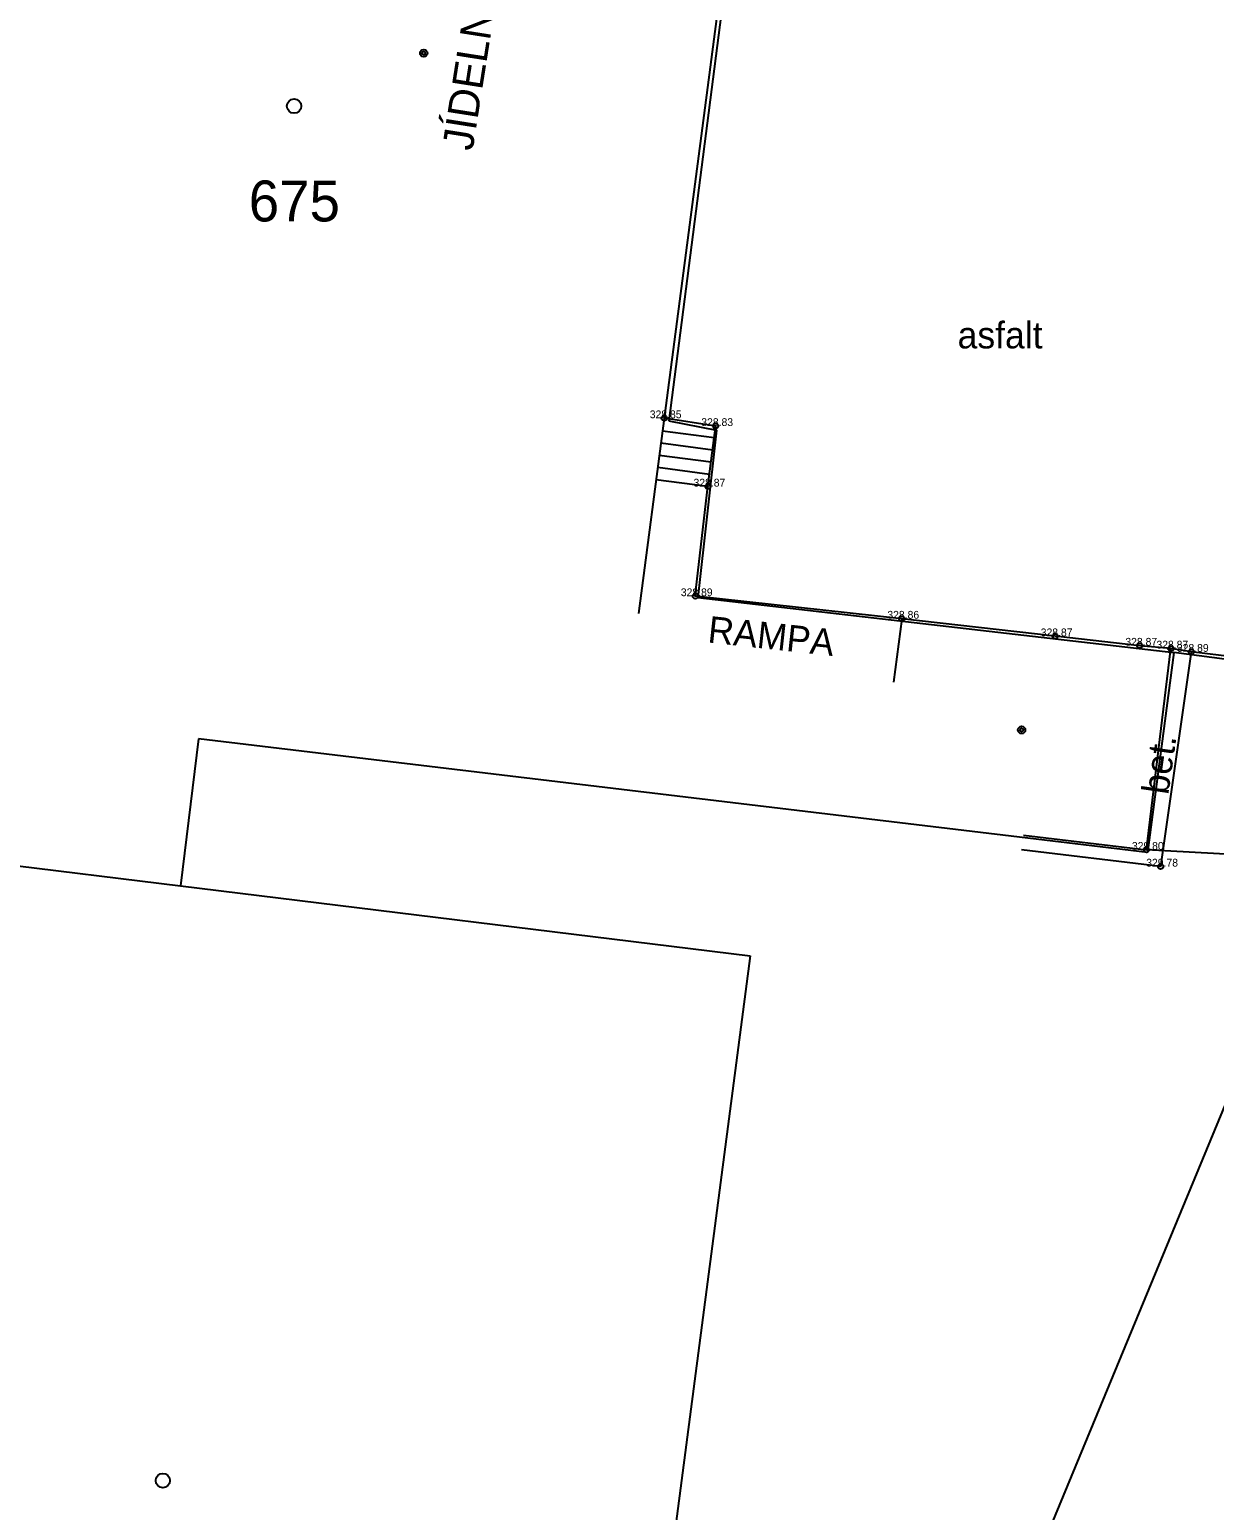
# Model space of a CAD drawing. Extents: x -643859 to -643594, y -1190913 to -1190609.
# Drawn here: x -643791.29 to -643762.32, y -1190846.99 to -1190810.79 of the extents above; entities that cross this region are included whole.
import ezdxf

# ---------------------------------------------------------------- set-up
doc = ezdxf.new("R2010")
doc.units = 0
for name, color, linetype in [('Bodové objekty značky budov', 7, 'Continuous'), ('Bodové objekty značky předmětů', 7, 'Continuous'), ('Budovy', 7, 'Continuous'), ('Default', 7, 'Continuous'), ('Hranice parcel', 7, 'Continuous'), ('Popis povrchů', 7, 'Continuous'), ('Rozhraní', 7, 'Continuous'), ('Rozhraní_ schody_ zdi', 7, 'Continuous'), ('Svodidla_zábradlí', 7, 'Continuous'), ('Vrstva 11', 7, 'Continuous'), ('Vrstva 63', 7, 'Continuous'), ('Vstup do objektu', 7, 'Continuous'), ('Vstup na pozemek', 7, 'Continuous')]:
    doc.layers.add(name, color=color, linetype=linetype)

msp = doc.modelspace()

# ---------------------------------------------------------------- linework, layer by layer
at = {"layer": 'Bodové objekty značky budov'}
for centre, radius in [((-643781.651, -1190811.365), 0.09), ((-643781.651, -1190811.365), 0.0398), ((-643767.03, -1190827.91), 0.09), ((-643767.03, -1190827.91), 0.0398)]:
    msp.add_circle(centre, radius, dxfattribs=at)
at = {"layer": 'Budovy'}
for points in [[(-643782.22, -1190797.98), (-643773.05, -1190799.15), (-643774.4, -1190809.83), (-643775.77, -1190820.29), (-643776.401, -1190825.062)], [(-643766.985, -1190830.481), (-643763.98, -1190830.84), (-643763.38, -1190825.92), (-643764.14, -1190825.85), (-643766.21, -1190825.62), (-643769.96, -1190825.19), (-643770.16, -1190826.738)]]:
    msp.add_lwpolyline(points, dxfattribs=at)
at = {"layer": 'Default'}
for centre in [(-643775.77, -1190820.29), (-643774.51, -1190820.48), (-643774.7, -1190821.96), (-643775.01, -1190824.64), (-643769.96, -1190825.19), (-643766.21, -1190825.62), (-643764.14, -1190825.85), (-643763.38, -1190825.92), (-643762.88, -1190826), (-643763.98, -1190830.84), (-643763.63, -1190831.25)]:
    msp.add_circle(centre, 0.0625, dxfattribs=at)
at = {"layer": 'Hranice parcel'}
for p, q in [((-643774.34, -1190810.1), (-643775.66, -1190820.35)), ((-643775.66, -1190820.35), (-643774.49, -1190820.58)), ((-643774.49, -1190820.58), (-643774.95, -1190824.67)), ((-643774.95, -1190824.67), (-643763.31, -1190826.02)), ((-643763.31, -1190826.02), (-643763.95, -1190830.91)), ((-643761.76, -1190826.22), (-643763.31, -1190826.02)), ((-643787.16, -1190828.13), (-643787.6, -1190831.72)), ((-643763.95, -1190830.91), (-643787.16, -1190828.13)), ((-643799.11, -1190830.31), (-643787.6, -1190831.72)), ((-643787.6, -1190831.72), (-643773.67, -1190833.43)), ((-643773.67, -1190833.43), (-643777.78, -1190864.8)), ((-643767.84, -1190851.05), (-643761.82, -1190836.51))]:
    msp.add_line(p, q, dxfattribs=at)
at = {"layer": 'Rozhraní'}
msp.add_lwpolyline([(-643754.88, -1190809.61), (-643755.42, -1190810.9), (-643755.66, -1190811.46), (-643755.95, -1190812.17), (-643756.19, -1190812.7), (-643756.52, -1190813.51), (-643756.73, -1190814.02), (-643757.01, -1190814.73), (-643757.26, -1190815.28), (-643757.61, -1190816.08), (-643757.76, -1190816.47), (-643758, -1190817.06), (-643758, -1190817.06), (-643758.04, -1190817.19), (-643758.21, -1190817.57), (-643758.29, -1190817.78), (-643758.49, -1190818.26), (-643758.54, -1190818.4), (-643759.07, -1190819.62), (-643759.39, -1190820.34), (-643759.6, -1190820.87), (-643761.82, -1190826.13), (-643762.88, -1190826), (-643763.38, -1190825.92)], dxfattribs=at)
at = {"layer": 'Rozhraní_ schody_ zdi'}
for p, q in [((-643774.544, -1190820.77), (-643775.811, -1190820.604)), ((-643774.583, -1190821.068), (-643775.851, -1190820.901)), ((-643774.661, -1190821.663), (-643775.929, -1190821.496)), ((-643774.622, -1190821.365), (-643775.89, -1190821.199)), ((-643774.7, -1190821.96), (-643775.971, -1190821.793))]:
    msp.add_line(p, q, dxfattribs=at)
for points in [[(-643769.96, -1190825.19), (-643775.01, -1190824.64), (-643774.7, -1190821.96), (-643774.544, -1190820.77), (-643774.51, -1190820.48), (-643775.77, -1190820.29)], [(-643762.88, -1190826), (-643763.63, -1190831.25), (-643767.029, -1190830.844)]]:
    msp.add_lwpolyline(points, dxfattribs=at)
at = {"layer": 'Vrstva 11'}
for centre in [(-643784.82, -1190812.66), (-643788.03, -1190846.26)]:
    msp.add_circle(centre, 0.175, dxfattribs=at)
at = {"layer": 'Vstup do objektu'}
msp.add_line((-643764.14, -1190825.85), (-643766.21, -1190825.62), dxfattribs=at)
at = {"layer": 'Vstup na pozemek'}
msp.add_line((-643761.74, -1190830.96), (-643763.98, -1190830.84), dxfattribs=at)

# ---------------------------------------------------------------- texts
at = {"layer": 'Bodové objekty značky předmětů'}
msp.add_text('JÍDELNA', height=0.75, rotation=81.0685, dxfattribs=at).set_placement((-643780.458, -1190813.772))
at = {"layer": 'Popis povrchů'}
msp.add_text('asfalt', height=0.65, dxfattribs=at).set_placement((-643768.595, -1190818.583))
for s, rotation, p in [('RAMPA', 353.7844, (-643774.724, -1190825.769)), ('bet.', 81.8699, (-643763.446, -1190829.511))]:
    msp.add_text(s, height=0.65, rotation=rotation, dxfattribs=at).set_placement(p)
at = {"layer": 'Svodidla_zábradlí'}
for s, p in [('328.85', (-643776.123, -1190820.29)), ('328.83', (-643774.863, -1190820.48)), ('328.87', (-643775.053, -1190821.96)), ('328.89', (-643775.363, -1190824.64)), ('328.86', (-643770.313, -1190825.19)), ('328.87', (-643766.563, -1190825.62)), ('328.87', (-643764.493, -1190825.85)), ('328.87', (-643763.733, -1190825.92)), ('328.89', (-643763.233, -1190826)), ('329.80', (-643764.333, -1190830.84)), ('329.78', (-643763.983, -1190831.25))]:
    msp.add_text(s, height=0.19, dxfattribs=at).set_placement(p)
at = {"layer": 'Vrstva 63'}
msp.add_text('675', height=1, dxfattribs=at).set_placement((-643785.929, -1190815.479))

doc.saveas('drawing.dxf')
